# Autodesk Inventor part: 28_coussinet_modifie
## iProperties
Created: 2002-11
Part Number: 28_coussinet_modifie
Material: Laiton (jaune doux)
Document SubType Name: Modélisation
Designer: FIEVET
Control State: 0
Master: False
Checked Out: False
Shininess: 20.0
Length Units: 11269
Angle Units: 11279
Time Units: 11290
Mass Units: 11283
Length Display Precision: 3
Angle Display Precision: 2
Compacted: True
Density: 8.47
Volumn: 1.1660203010094004
Area: 12.835695409738756
PropertySet Name: Model Information
Author: FIEVET
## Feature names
1. Révolution1 [Revolution]
